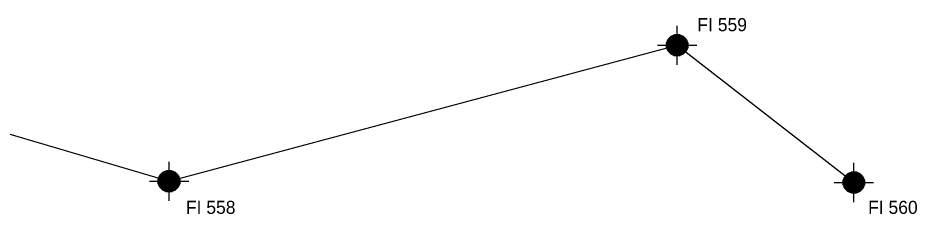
# Model space of a CAD drawing. Extents: x -346533 to -339969, y -1273090 to -1271585.
# Drawn here: x -340484 to -339969, y -1271698 to -1271585 of the extents above; entities that cross this region are included whole.
import ezdxf

# ---------------------------------------------------------------- set-up
doc = ezdxf.new("R2010")
doc.units = 0
for name, color, linetype in [('BP_11', 7, 'Continuous'), ('BP_12', 7, 'Continuous'), ('BP_14', 7, 'Continuous')]:
    doc.layers.add(name, color=color, linetype=linetype)

msp = doc.modelspace()

# ---------------------------------------------------------------- linework, layer by layer
at = {"layer": 'BP_11'}
for points in [[(-340106.11, -1271612.19), (-340106.11, -1271605.84), (-340106.11, -1271599.49), (-340106.11, -1271593.14), (-340106.11, -1271589.69)], [(-340106.11, -1271594.79), (-340104.91, -1271594.79), (-340102.66, -1271595.74), (-340100.96, -1271597.44), (-340100.01, -1271599.69), (-340100.01, -1271602.14), (-340100.96, -1271604.39), (-340102.66, -1271606.09), (-340104.91, -1271607.04), (-340107.36, -1271607.04), (-340109.61, -1271606.09), (-340111.31, -1271604.39), (-340112.26, -1271602.14), (-340112.26, -1271599.69), (-340111.31, -1271597.44), (-340109.61, -1271595.74), (-340107.36, -1271594.79), (-340106.16, -1271594.79), (-340104.36, -1271595.14), (-340107.96, -1271595.14), (-340108.76, -1271595.54), (-340103.56, -1271595.54), (-340102.76, -1271595.94), (-340109.11, -1271595.94), (-340109.56, -1271595.94), (-340109.96, -1271596.34), (-340103.61, -1271596.34), (-340102.36, -1271596.34), (-340101.96, -1271596.74), (-340108.31, -1271596.74), (-340110.36, -1271596.74), (-340110.76, -1271597.14), (-340104.41, -1271597.14), (-340101.56, -1271597.14), (-340101.16, -1271597.54), (-340107.51, -1271597.54), (-340111.16, -1271597.54), (-340111.16, -1271597.94), (-340104.81, -1271597.94), (-340101.16, -1271597.94), (-340100.76, -1271598.34), (-340107.11, -1271598.34), (-340111.56, -1271598.34), (-340111.56, -1271598.74), (-340105.21, -1271598.74), (-340100.76, -1271598.74), (-340100.36, -1271599.14), (-340106.71, -1271599.14), (-340111.96, -1271599.14), (-340111.96, -1271599.54), (-340105.61, -1271599.54), (-340100.36, -1271599.54), (-340100.36, -1271599.94), (-340106.71, -1271599.94), (-340111.96, -1271599.94), (-340111.96, -1271600.34), (-340105.61, -1271600.34), (-340100.36, -1271600.34), (-340100.36, -1271600.74), (-340106.71, -1271600.74), (-340111.96, -1271600.74), (-340111.96, -1271601.14), (-340105.61, -1271601.14), (-340100.36, -1271601.14), (-340100.36, -1271601.54), (-340106.71, -1271601.54), (-340111.96, -1271601.54), (-340111.96, -1271601.94), (-340105.61, -1271601.94), (-340100.36, -1271601.94), (-340100.36, -1271602.34), (-340106.71, -1271602.34), (-340111.96, -1271602.34), (-340111.96, -1271602.74), (-340105.61, -1271602.74), (-340100.36, -1271602.74), (-340100.76, -1271603.14), (-340107.11, -1271603.14), (-340111.56, -1271603.14), (-340111.56, -1271603.54), (-340105.21, -1271603.54), (-340100.76, -1271603.54), (-340101.16, -1271603.94), (-340107.51, -1271603.94), (-340111.16, -1271603.94), (-340111.16, -1271604.34), (-340104.81, -1271604.34), (-340101.16, -1271604.34), (-340101.56, -1271604.74), (-340107.91, -1271604.74), (-340110.76, -1271604.74), (-340110.36, -1271605.14), (-340104.01, -1271605.14), (-340101.96, -1271605.14), (-340102.36, -1271605.54), (-340108.71, -1271605.54), (-340109.96, -1271605.54), (-340109.56, -1271605.94), (-340103.21, -1271605.94), (-340102.76, -1271605.94)], [(-340117.36, -1271600.94), (-340111.01, -1271600.94), (-340104.66, -1271600.94), (-340098.31, -1271600.94), (-340094.86, -1271600.94)], [(-340102.76, -1271605.94), (-340103.56, -1271606.34), (-340108.76, -1271606.34), (-340107.96, -1271606.74), (-340104.36, -1271606.74)], [(-340397.23, -1271690.27), (-340397.23, -1271683.92), (-340397.23, -1271677.57), (-340397.23, -1271671.22), (-340397.23, -1271667.77)], [(-340004.87, -1271691), (-340004.87, -1271684.65), (-340004.87, -1271678.3), (-340004.87, -1271671.95), (-340004.87, -1271668.5)], [(-340397.23, -1271672.87), (-340396.03, -1271672.87), (-340393.78, -1271673.82), (-340392.08, -1271675.52), (-340391.13, -1271677.77), (-340391.13, -1271680.22), (-340392.08, -1271682.47), (-340393.78, -1271684.17), (-340396.03, -1271685.12), (-340398.48, -1271685.12), (-340400.73, -1271684.17), (-340402.43, -1271682.47), (-340403.38, -1271680.22), (-340403.38, -1271677.77), (-340402.43, -1271675.52), (-340400.73, -1271673.82), (-340398.48, -1271672.87), (-340397.28, -1271672.87), (-340395.48, -1271673.22), (-340399.08, -1271673.22), (-340399.88, -1271673.62), (-340394.68, -1271673.62), (-340393.88, -1271674.02), (-340400.23, -1271674.02), (-340400.68, -1271674.02), (-340401.08, -1271674.42), (-340394.73, -1271674.42), (-340393.48, -1271674.42), (-340393.08, -1271674.82), (-340399.43, -1271674.82), (-340401.48, -1271674.82), (-340401.88, -1271675.22), (-340395.53, -1271675.22), (-340392.68, -1271675.22), (-340392.28, -1271675.62), (-340398.63, -1271675.62), (-340402.28, -1271675.62), (-340402.28, -1271676.02), (-340395.93, -1271676.02), (-340392.28, -1271676.02), (-340391.88, -1271676.42), (-340398.23, -1271676.42), (-340402.68, -1271676.42), (-340402.68, -1271676.82), (-340396.33, -1271676.82), (-340391.88, -1271676.82), (-340391.48, -1271677.22), (-340397.83, -1271677.22), (-340403.08, -1271677.22), (-340403.08, -1271677.62), (-340396.73, -1271677.62), (-340391.48, -1271677.62), (-340391.48, -1271678.02), (-340397.83, -1271678.02), (-340403.08, -1271678.02), (-340403.08, -1271678.42), (-340396.73, -1271678.42), (-340391.48, -1271678.42), (-340391.48, -1271678.82), (-340397.83, -1271678.82), (-340403.08, -1271678.82), (-340403.08, -1271679.22), (-340396.73, -1271679.22), (-340391.48, -1271679.22), (-340391.48, -1271679.62), (-340397.83, -1271679.62), (-340403.08, -1271679.62), (-340403.08, -1271680.02), (-340396.73, -1271680.02), (-340391.48, -1271680.02), (-340391.48, -1271680.42), (-340397.83, -1271680.42), (-340403.08, -1271680.42), (-340403.08, -1271680.82), (-340396.73, -1271680.82), (-340391.48, -1271680.82), (-340391.88, -1271681.22), (-340398.23, -1271681.22), (-340402.68, -1271681.22), (-340402.68, -1271681.62), (-340396.33, -1271681.62), (-340391.88, -1271681.62), (-340392.28, -1271682.02), (-340398.63, -1271682.02), (-340402.28, -1271682.02), (-340402.28, -1271682.42), (-340395.93, -1271682.42), (-340392.28, -1271682.42), (-340392.68, -1271682.82), (-340399.03, -1271682.82), (-340401.88, -1271682.82), (-340401.48, -1271683.22), (-340395.13, -1271683.22), (-340393.08, -1271683.22), (-340393.48, -1271683.62), (-340399.83, -1271683.62), (-340401.08, -1271683.62), (-340400.68, -1271684.02), (-340394.33, -1271684.02), (-340393.88, -1271684.02)], [(-340004.87, -1271673.6), (-340003.67, -1271673.6), (-340001.42, -1271674.55), (-339999.72, -1271676.25), (-339998.77, -1271678.5), (-339998.77, -1271680.95), (-339999.72, -1271683.2), (-340001.42, -1271684.9), (-340003.67, -1271685.85), (-340006.12, -1271685.85), (-340008.37, -1271684.9), (-340010.07, -1271683.2), (-340011.02, -1271680.95), (-340011.02, -1271678.5), (-340010.07, -1271676.25), (-340008.37, -1271674.55), (-340006.12, -1271673.6), (-340004.92, -1271673.6), (-340003.12, -1271673.95), (-340006.72, -1271673.95), (-340007.52, -1271674.35), (-340002.32, -1271674.35), (-340001.52, -1271674.75), (-340007.87, -1271674.75), (-340008.32, -1271674.75), (-340008.72, -1271675.15), (-340002.37, -1271675.15), (-340001.12, -1271675.15), (-340000.72, -1271675.55), (-340007.07, -1271675.55), (-340009.12, -1271675.55), (-340009.52, -1271675.95), (-340003.17, -1271675.95), (-340000.32, -1271675.95), (-339999.92, -1271676.35), (-340006.27, -1271676.35), (-340009.92, -1271676.35), (-340009.92, -1271676.75), (-340003.57, -1271676.75), (-339999.92, -1271676.75), (-339999.52, -1271677.15), (-340005.87, -1271677.15), (-340010.32, -1271677.15), (-340010.32, -1271677.55), (-340003.97, -1271677.55), (-339999.52, -1271677.55), (-339999.12, -1271677.95), (-340005.47, -1271677.95), (-340010.72, -1271677.95), (-340010.72, -1271678.35), (-340004.37, -1271678.35), (-339999.12, -1271678.35), (-339999.12, -1271678.75), (-340005.47, -1271678.75), (-340010.72, -1271678.75), (-340010.72, -1271679.15), (-340004.37, -1271679.15), (-339999.12, -1271679.15), (-339999.12, -1271679.55), (-340005.47, -1271679.55), (-340010.72, -1271679.55), (-340010.72, -1271679.95), (-340004.37, -1271679.95), (-339999.12, -1271679.95), (-339999.12, -1271680.35), (-340005.47, -1271680.35), (-340010.72, -1271680.35), (-340010.72, -1271680.75), (-340004.37, -1271680.75), (-339999.12, -1271680.75), (-339999.12, -1271681.15), (-340005.47, -1271681.15), (-340010.72, -1271681.15), (-340010.72, -1271681.55), (-340004.37, -1271681.55), (-339999.12, -1271681.55), (-339999.52, -1271681.95), (-340005.87, -1271681.95), (-340010.32, -1271681.95), (-340010.32, -1271682.35), (-340003.97, -1271682.35), (-339999.52, -1271682.35), (-339999.92, -1271682.75), (-340006.27, -1271682.75), (-340009.92, -1271682.75), (-340009.92, -1271683.15), (-340003.57, -1271683.15), (-339999.92, -1271683.15), (-340000.32, -1271683.55), (-340006.67, -1271683.55), (-340009.52, -1271683.55), (-340009.12, -1271683.95), (-340002.77, -1271683.95), (-340000.72, -1271683.95), (-340001.12, -1271684.35), (-340007.47, -1271684.35), (-340008.72, -1271684.35), (-340008.32, -1271684.75), (-340001.97, -1271684.75), (-340001.52, -1271684.75)], [(-340408.48, -1271679.02), (-340402.13, -1271679.02), (-340395.78, -1271679.02), (-340389.43, -1271679.02), (-340385.98, -1271679.02)], [(-340393.88, -1271684.02), (-340394.68, -1271684.42), (-340399.88, -1271684.42), (-340399.08, -1271684.82), (-340395.48, -1271684.82)], [(-340016.12, -1271679.75), (-340009.77, -1271679.75), (-340003.42, -1271679.75), (-339997.07, -1271679.75), (-339993.62, -1271679.75)], [(-340001.52, -1271684.75), (-340002.32, -1271685.15), (-340007.52, -1271685.15), (-340006.72, -1271685.55), (-340003.12, -1271685.55)]]:
    msp.add_lwpolyline(points, dxfattribs=at)
for points in [[(-340104.91, -1271594.79), (-340102.66, -1271595.74), (-340100.96, -1271597.44), (-340100.01, -1271599.69), (-340100.01, -1271602.14), (-340100.96, -1271604.39), (-340102.66, -1271606.09), (-340104.91, -1271607.04), (-340107.36, -1271607.04), (-340109.61, -1271606.09), (-340111.31, -1271604.39), (-340112.26, -1271602.14), (-340112.26, -1271599.69), (-340111.31, -1271597.44), (-340109.61, -1271595.74), (-340107.36, -1271594.79)], [(-340396.03, -1271672.87), (-340393.78, -1271673.82), (-340392.08, -1271675.52), (-340391.13, -1271677.77), (-340391.13, -1271680.22), (-340392.08, -1271682.47), (-340393.78, -1271684.17), (-340396.03, -1271685.12), (-340398.48, -1271685.12), (-340400.73, -1271684.17), (-340402.43, -1271682.47), (-340403.38, -1271680.22), (-340403.38, -1271677.77), (-340402.43, -1271675.52), (-340400.73, -1271673.82), (-340398.48, -1271672.87)], [(-340003.67, -1271673.6), (-340001.42, -1271674.55), (-339999.72, -1271676.25), (-339998.77, -1271678.5), (-339998.77, -1271680.95), (-339999.72, -1271683.2), (-340001.42, -1271684.9), (-340003.67, -1271685.85), (-340006.12, -1271685.85), (-340008.37, -1271684.9), (-340010.07, -1271683.2), (-340011.02, -1271680.95), (-340011.02, -1271678.5), (-340010.07, -1271676.25), (-340008.37, -1271674.55), (-340006.12, -1271673.6)]]:
    msp.add_lwpolyline(points, close=True, dxfattribs=at)
at = {"layer": 'BP_14'}
for p, q in [((-340397.23, -1271679.02), (-340106.11, -1271600.94)), ((-340106.11, -1271600.94), (-340004.87, -1271679.75)), ((-340643.57, -1271606.07), (-340397.23, -1271679.02))]:
    msp.add_line(p, q, dxfattribs=at)

# ---------------------------------------------------------------- texts
at = {"layer": 'BP_12'}
for s, p in [('FI 559', (-340094.57, -1271592.86)), ('FI 558', (-340387.59, -1271697.74)), ('FI 560', (-339996.77, -1271697.74))]:
    msp.add_text(s, height=7.5, dxfattribs=at).set_placement(p)

doc.saveas('drawing.dxf')
